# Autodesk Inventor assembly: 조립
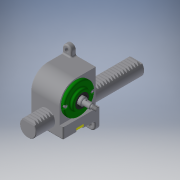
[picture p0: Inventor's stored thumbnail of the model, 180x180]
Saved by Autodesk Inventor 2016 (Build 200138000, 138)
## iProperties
Created: 2019-06
Part Number: 조립
Material: 일반
Document SubType Name: Assembly
Designer: 605-11
Author: 605-11
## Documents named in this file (10)
- C:\Users\605-11\Documents\조립.iam
- C:\Users\605-11\Desktop\390604v1036\본체.ipt
- C:\Users\605-11\Desktop\390604v1036\누름쇠.ipt
- C:\Users\605-11\Desktop\390604v1036\뒤커버.ipt
- C:\Users\605-11\Desktop\390604v1036\래크.ipt
- C:\Users\605-11\Desktop\390604v1036\베어링 6003.ipt
- C:\Users\605-11\Desktop\390604v1036\볼트 M4.ipt
- C:\Users\605-11\Desktop\390604v1036\앞커버.ipt
- C:\Users\605-11\Desktop\390604v1036\오일 실 17 30 5.ipt
- C:\Users\605-11\Desktop\390604v1036\피니언.ipt
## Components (1 placed, 1 different names)
1. 피니언:1 — 각도:4
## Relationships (1: Angle 1)
- 각도:4 [Angle]: 피니언:1
